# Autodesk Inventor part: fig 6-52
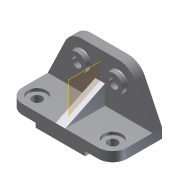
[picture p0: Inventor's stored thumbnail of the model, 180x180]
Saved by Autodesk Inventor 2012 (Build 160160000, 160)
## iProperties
Shininess: 77.0
Length Units: 11269
Angle Units: 11279
Time Units: 11290
Mass Units: 11283
Length Display Precision: 3
Angle Display Precision: 2
Created: 2001-12
Part Number: fig 6-52
Document SubType Name: Modeling
Designer: Renu Muthoo
Density: 1 g/cm^3
Material: Default
Density: 0.0
Volumn: 0.0
Area: 0.0
PropertySet Name: Model Information
Control State: 0
Master: False
Checked Out: False
Author: Renu Muthoo
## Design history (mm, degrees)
node "Sketch1"
sketch "Sketch2"
  geometry: L1 (-67.219, 19.116)-(148.781, 19.116); L2 (148.781, 19.116)-(148.781, -0.884); L3 (-67.219, -0.884)-(-67.219, 19.116); L4 (-10.219, -0.884)-(-10.219, -9.884); L5 (-10.219, -9.884)-(91.781, -9.884); L6 (91.781, -9.884)-(91.781, -0.884); L7 (148.781, -0.884)-(91.781, -0.884); L8 (-10.219, -0.884)-(-67.219, -0.884)
  constraints: 16 end point, 5 parallel, 4 perpendicular, 2 equal length, 1 horizontal
  dimensions: "d0" = 102 distance of L4.end L5.end; "d1" = 57 distance of L4.start L3.start; "d2" = 29 distance between parallel lines of L1 L5; "d3" = 20 distance of L1.end L2.end
extrude "Extrusion1" new body sketch "Sketch2" distance "d4" = 102; taper "d5" = 0 deg
sketch "Sketch3"
  geometry: L1 (67.219, -19.116)-(-148.781, -19.116) reference; L2 (67.219, -19.116)-(31.475, -93.564); L3 (-2.781, -115.116)-(-78.781, -115.116); L4 (-113.038, -93.564)-(-148.781, -19.116); A1 r 38 centre (-2.781, -77.116) between (-2.781, -115.116) and (31.475, -93.564); A2 r 38 centre (-78.781, -77.116) between (-113.038, -93.564) and (-78.781, -115.116)
  constraints: 6 end point, 4 point on circle, 4 tangent, 2 centre point, 1 equal length, 1 equal radius, 1 parallel
  dimensions: "d6" = 96 distance between parallel lines of L3 L1; "d7" = 38 radius of A1; "d8" = 76 distance of A2.centre A1.centre
extrude "Extrusion2" join sketch "Sketch3" distance "d9" = 20; taper "d10" = 0 deg
fillet "Fillet1" dims "d11" = 30
workplane "Work Plane1"
sketch "Sketch5"
  geometry: A1 r 30 centre (-30, 0) between (-30, -30) and (0, 0) reference; 1 further point
  constraints: 1 coincident
hole "Hole1" sketch "Sketch5" at (-30, 0) diameter "d16" = 20; stored, may be unused: countersink angle "d20" = 82 deg, drill point angle "d22" = 118 deg; dims "d17" = 6, "d18" = 38, "d19" = 6, "d21" = 8
sketch "Sketch6"
  geometry: C1 r 19 at (-2.781, 77.116); C2 r 9.5 at (-2.781, 77.116); A1 r 38 centre (-2.781, 77.116) between (31.475, 93.564) and (-2.781, 115.116) reference
  constraints: 2 centre point, 2 coincident
  dimensions: "d23" = 38 diameter of C1; "d24" = 19 diameter of C2
extrude "Extrusion3" join sketch "Sketch6" distance "d25" = 10; taper "d26" = 0 deg
sketch "Sketch7"
  geometry: L1 (0, -82)-(-39.557, 0); L2 (0, -82)-(20, -82) reference; L3 (29, 22.405)-(29, -82); L4 (29, -82)-(0, -82); L5 (0, -82)-(0, 0); L6 (0, 0)-(-90.034, 0); L7 (-90.034, 0)-(-90.034, 22.405); L8 (-90.034, 22.405)-(29, 22.405); L9 (0, 0)-(-74.447, 0) reference
  constraints: 14 end point, 1 collinear, 1 point on line
feature "Rib3" sketch "Sketch7" dims "d35" = 10, "d36" = 20
fillet "Fillet3" dims "d37" = 2
mirror "Mirror4"
body "Solid1"
other parameters: "d12" = -108
